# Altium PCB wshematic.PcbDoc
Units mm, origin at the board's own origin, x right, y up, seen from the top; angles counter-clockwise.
Board outline 234.44 x 166.12 mm, 2 copper layers (Top Layer, Bottom Layer); 41 components, 0 nets, 191 pads, 0 vias.
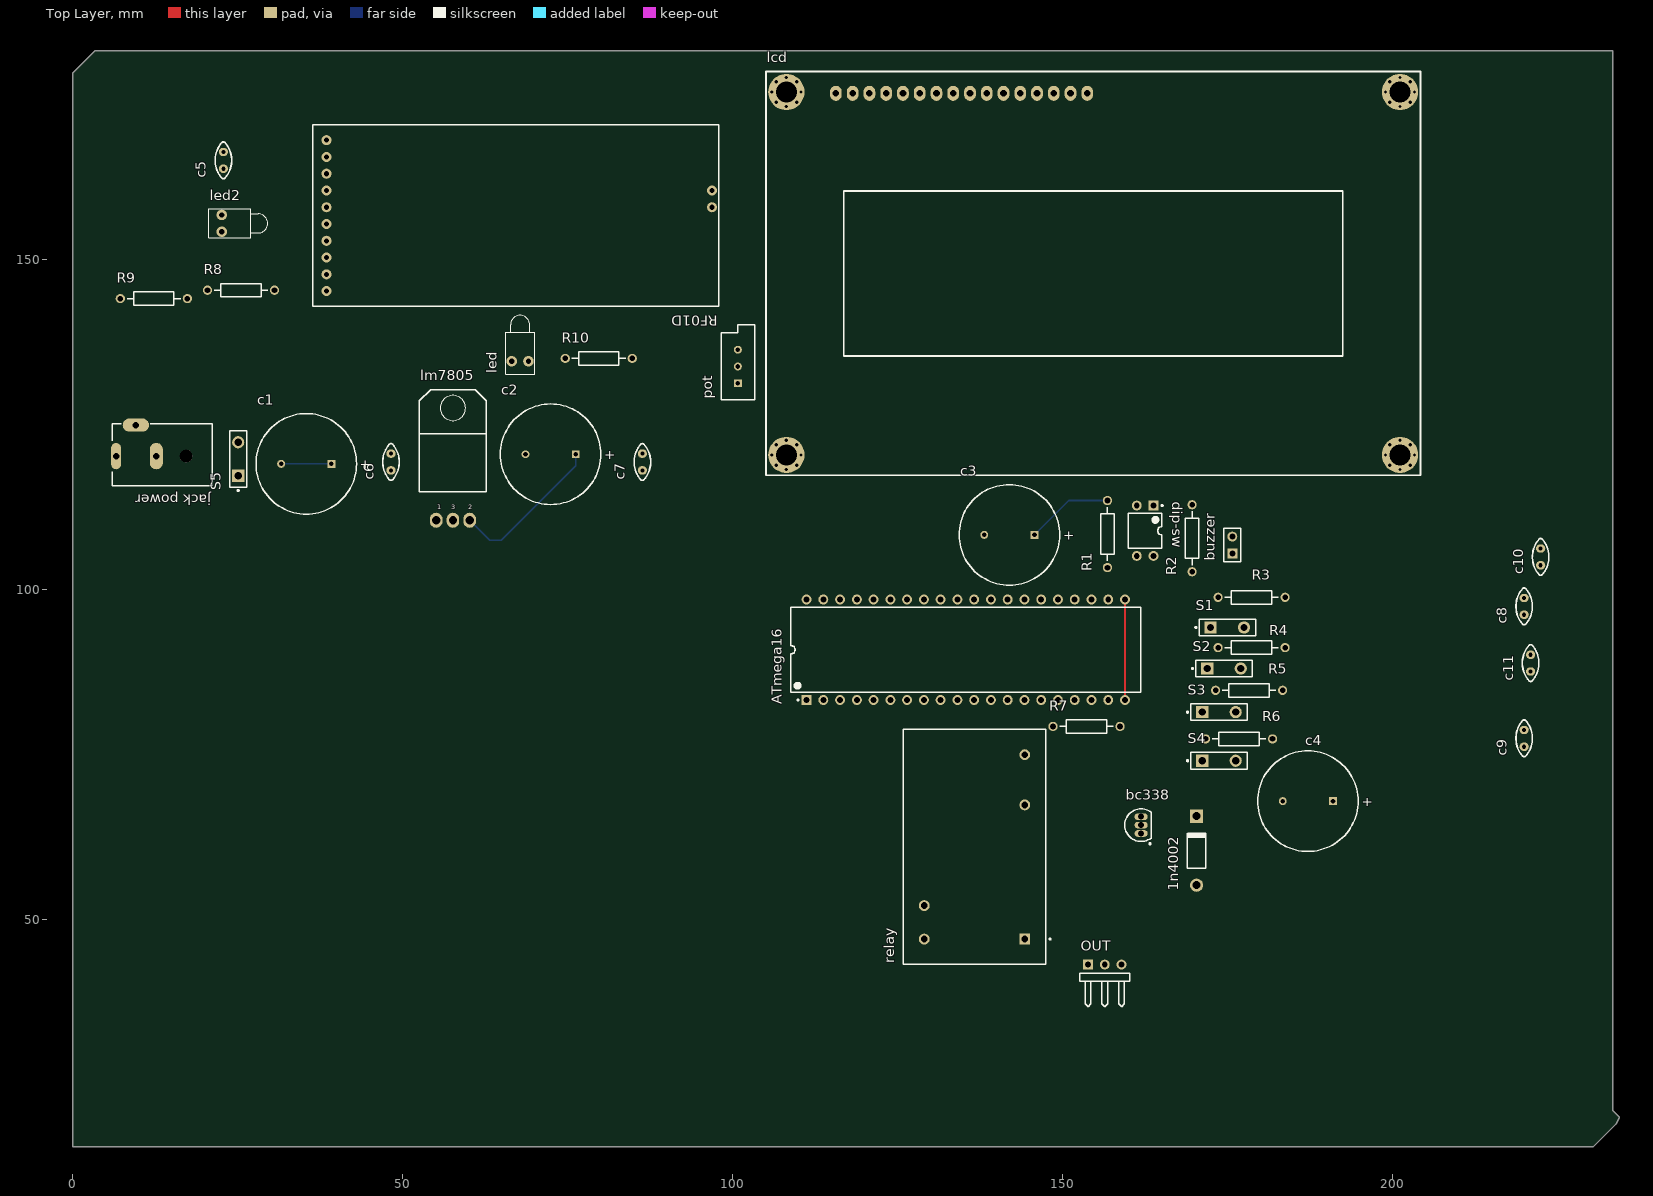
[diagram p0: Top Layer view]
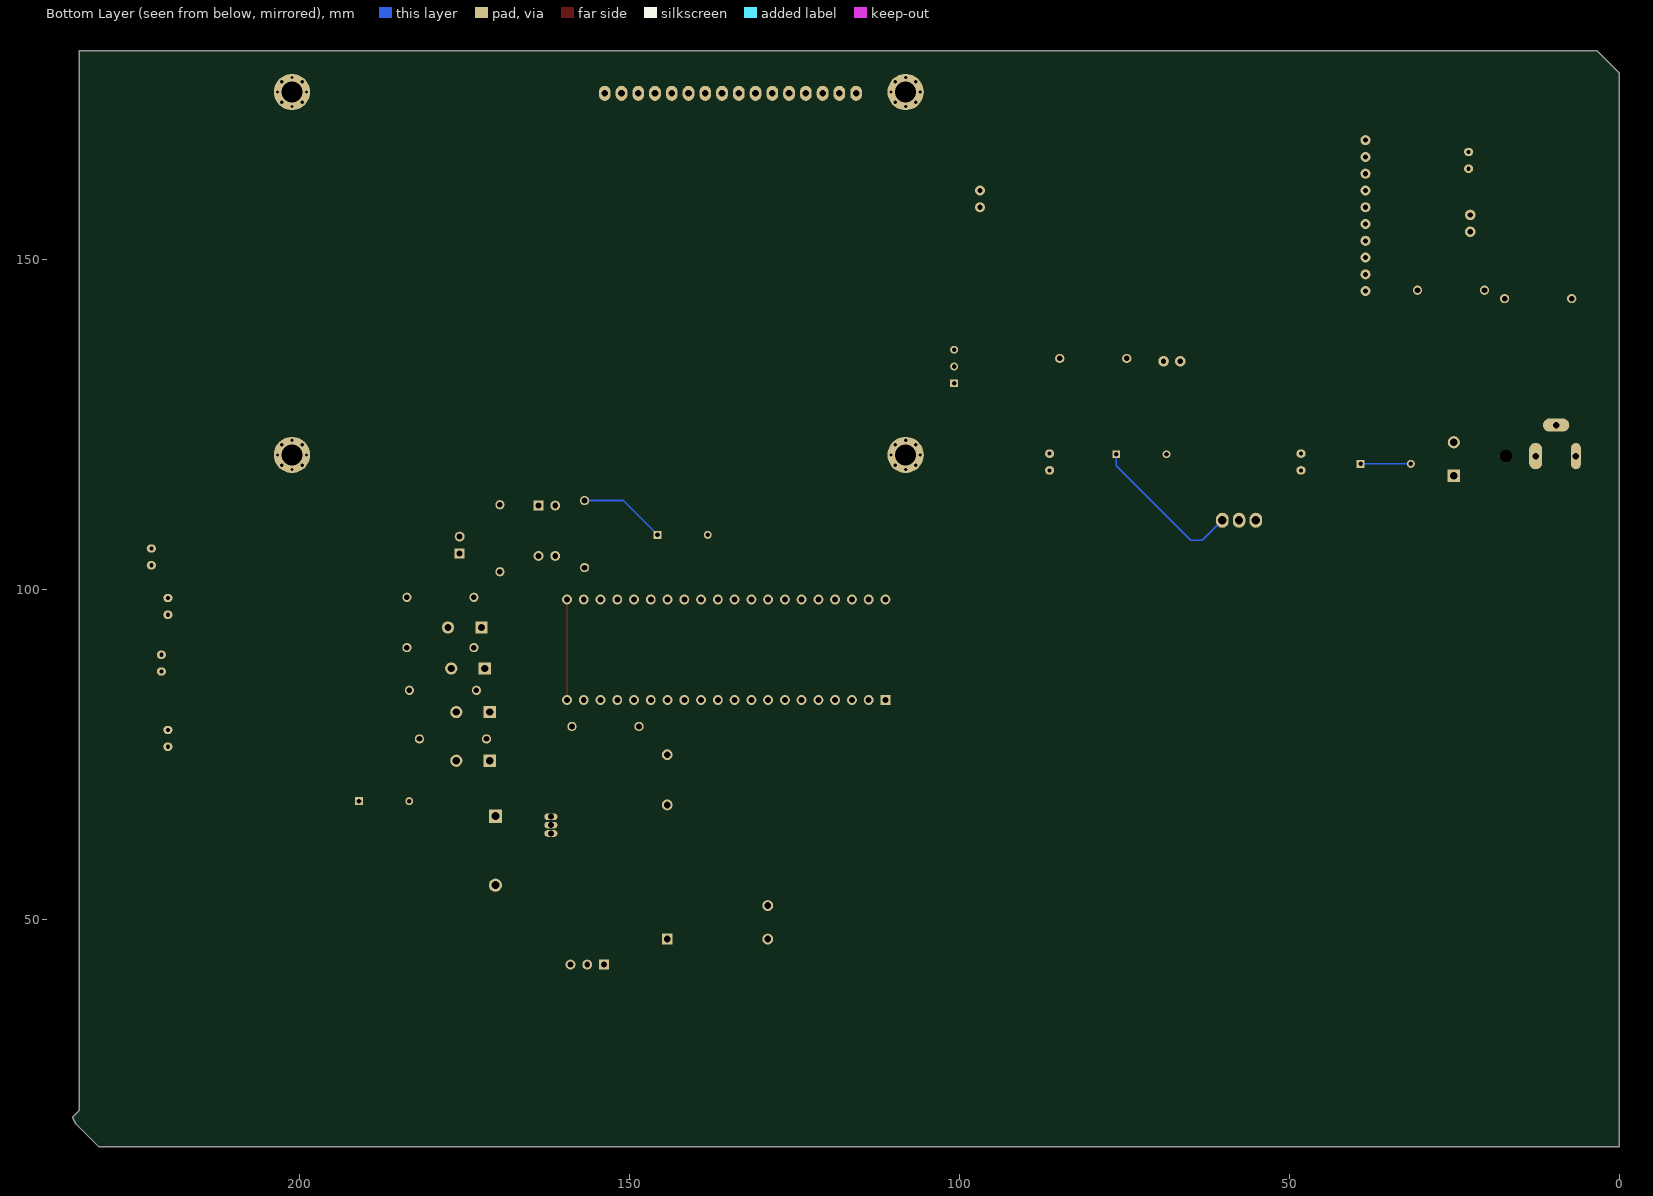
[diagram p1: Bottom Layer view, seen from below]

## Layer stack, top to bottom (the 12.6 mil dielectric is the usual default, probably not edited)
Top Layer: signal copper 0.0356
Dielectric: dielectric 0.32, FR-4, Dk 4.8
Bottom Layer: signal copper 0.0356

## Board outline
234.442,20.066 233.426,21.082 233.426,181.737 3.429,181.737 0,178.308 0,15.621 230.505,15.621 233.934,19.05

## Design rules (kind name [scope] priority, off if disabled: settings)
Clearance [All] p1: gap=0.254
Height [All] p1: minheight=0 maxheight=64 prefheight=12.7
PolygonConnect [All] p1: connectstyle=Relief reliefconductorwidth=0.254 reliefentries=4 polygonreliefangle="90 Angle"
RoutingVias [All] p1: holewidth=0.711 width=1.27 viastyle="Through Hole" minholewidth=0.711 minwidth=1.27 maxholewidth=0.711 maxwidth=1.27
SilkscreenOverComponentPads [All] p1: minsilkscreentomaskgap=0.254
SolderMaskExpansion [All] p1: expansion=0.102
TestPointUsage FabricationTestPointUsage [All] p1: valid=0 allowmultiple=FALSE
Testpoint FabricationTestpoint [All] p1: side=3 testpointundercomponent=TRUE minsize=1.016 maxsize=2.54 preferedsize=1.524 minholesize=0 maxholesize=1.016 preferedholesize=0.813 testpointgrid=0.025 style=297 order=0123456789
Width [All] p1: maxlimit=0.254 minlimit=0.254 preferedwidth=0.254
22 further rules are at their usual default settings.

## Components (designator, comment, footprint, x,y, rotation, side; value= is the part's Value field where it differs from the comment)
1n4002 "Comment" DO-41 170.35,60.475 r90 top
ATmega16 "Comment" 40P6 135.375,90.925 r90 top
bc338 "Comment" TO-92A 161.95,64.35 r0 top
buzzer "Comment" HDR1X2 175.768,105.537 r90 top
c1 "Comment" RB7.6-15 35.425,119.1 r0 top
c2 "Comment" RB7.6-15 72.45,120.55 r0 top
c3 "Comment" RB7.6-15 141.986,108.331 r0 top
c4 "Comment" RB7.6-15 187.225,67.975 r0 top
c5 "Comment" "Cap - 100nF" 22.86,165.1 r90 top
c6 "Comment" "Cap - 100nF" 48.26,119.38 r90 top
c7 "Comment" "Cap - 100nF" 86.36,119.38 r90 top
c8 "Comment" "Cap - 100nF" 220,97.5 r90 top
c9 "Comment" "Cap - 100nF" 220,77.5 r90 top
c10 "Comment" "Cap - 100nF" 222.5,105 r90 top
c11 "Comment" "Cap - 100nF" 220.98,88.9 r90 top
Designator73 "Comment" PCBComponent_1#1 48.05,81.475 r0 top
dip-sw "Comment" DIP-4 162.56,108.966 r270 top
"jack power" "Comment" "Power Jack" 21.2,120.275 r180 top
lcd "Comment" "LCD 20x4" 154.686,147.955 r0 top
led "Comment" LED-1 67.825,134.65 r90 top
led2 "Comment" LED-1 22.625,155.55 r0 top
lm7805 "Comment" "78XXCV - Right" 57.65,110.55 r0 top
OUT "Comment" HDR1X3H 153.9,43.2 r0 top
pot "Comment" VR5 100.838,133.858 r90 top
R1 "Comment" AXIAL-0.4 156.845,108.458 r90 top
R2 "Comment" AXIAL-0.4 169.672,107.823 r90 top
R3 "Comment" AXIAL-0.4 178.693,98.872 r0 top
R4 "Comment" AXIAL-0.4 178.693,91.252 r0 top
R5 "Comment" AXIAL-0.4 178.312,84.775 r0 top
R6 "Comment" AXIAL-0.4 176.788,77.409 r0 top
R7 "Comment" AXIAL-0.4 153.675,79.3 r0 top
R8 "Comment" AXIAL-0.4 25.527,145.415 r0 top
R9 "Comment" AXIAL-0.4 12.319,144.145 r0 top
R10 "Comment" AXIAL-0.4 79.75,135.075 r0 top
relay "Comment" MODULE5B 136.7,61.05 r90 top
RF01D "Comment" PCBComponent_1#2 66.421,157.988 r180 top
S1 "Comment" SPST-2 175.01,94.3 r0 top
S2 "Comment" SPST-2 174.502,88.077 r0 top
S3 "Comment" SPST-2 173.74,81.473 r0 top
S4 "Comment" SPST-2 173.74,74.107 r0 top
S5 "Comment" SPST-2 25.1,119.825 r90 top

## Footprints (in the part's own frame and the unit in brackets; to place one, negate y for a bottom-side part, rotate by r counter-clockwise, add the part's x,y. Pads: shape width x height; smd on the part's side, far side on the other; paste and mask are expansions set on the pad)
40P6 [mm] "DIP, 40-Leads, Row Spacing 15.24mm, Pitch 2.54mm, Body 52.2x13.95mm"
  rect 1.5x1.5 hole 0.9: 1(-7.62,24.13)
  round 1.5 hole 0.9: 2(-7.62,21.59) 3(-7.62,19.05) 4(-7.62,16.51) 5(-7.62,13.97) 6(-7.62,11.43) 7(-7.62,8.89) 8(-7.62,6.35) 9(-7.62,3.81) 10(-7.62,1.27) 11(-7.62,-1.27) 12(-7.62,-3.81) 13(-7.62,-6.35) 14(-7.62,-8.89) 15(-7.62,-11.43) 16(-7.62,-13.97) 17(-7.62,-16.51) 18(-7.62,-19.05) 19(-7.62,-21.59) 20(-7.62,-24.13) 21(7.62,-24.13) 22(7.62,-21.59) 23(7.62,-19.05) 24(7.62,-16.51) 25(7.62,-13.97) 26(7.62,-11.43) 27(7.62,-8.89) 28(7.62,-6.35) 29(7.62,-3.81) 30(7.62,-1.27) 31(7.62,1.27) 32(7.62,3.81) 33(7.62,6.35) 34(7.62,8.89) 35(7.62,11.43) 36(7.62,13.97) 37(7.62,16.51) 38(7.62,19.05) 39(7.62,21.59) 40(7.62,24.13)
  silkscreen extent -7.74,-26.5 6.45,26.5, body extent -7.05,-26.47 7.05,26.47, height 4.83
"78XXCV - Right" [mil] "Right Angle"
  oval 75x90 hole 50: 1(-100,0) 2(100,0) 3(0,0)
  silkscreen extent -201,170 200,780, body extent -198,-8 202,776, height 175
AXIAL-0.4 [mm] "Axial Device, Thru-Hole; 2 Leads; 0.4 in Pin Spacing"
  round 1.4 hole 0.85: 1(-5.08,0) 2(5.08,0)
  silkscreen extent -4.06,-1.02 4.06,1.02
"Cap - 100nF" [mil]
  oval 50x55 hole 25: 1(-50,0) 2(50,0)
  silkscreen extent -110,-49 110,49, body extent -115,-34 115,33, height 272
DIP-4 [mm] "DIP; 4 Leads; Row Spacing 7.62 mm; Pitch 2.54 mm"
  rect 1.5x1.5 hole 0.9: 1(-3.81,1.27)
  round 1.5 hole 0.9: 2(-3.81,-1.27) 3(3.81,-1.27) 4(3.81,1.27)
  silkscreen extent -3.93,-2.55 2.65,2.7, body extent -3.15,-2.5 3.15,2.5, height 5.6
DO-41 [mm] "Diode, Axial; Body 5.2 x 2.7 mm (LxDia. max), Lead Dia. 0.86 mm (max)"
  round 2 hole 1.2: 1(-5.23,0)
  rect 2x2 hole 1.2: 2(5.23,0)
  silkscreen extent -2.65,-1.4 2.75,1.4
HDR1X2 [mm] "Connector; Header; 2 Position"
  rect 1.5x1.5 hole 0.9: 1(0,0)
  round 1.5 hole 0.9: 2(2.54,0)
  silkscreen extent -1.27,-1.27 3.81,1.27
HDR1X3H [mm] "Connector; Header; 3 Position; Right Angle"
  rect 1.5x1.5 hole 0.9: 1(0,0)
  round 1.5 hole 0.9: 2(2.54,0) 3(5.08,0)
  silkscreen extent -1.27,-6.35 6.35,-1.27
"LCD 20x4" [mm]
  oval 1.778x2.286 hole 1.016: 1(-39,27.3) 2(-36.46,27.3) 3(-33.92,27.3) 4(-31.38,27.3) 5(-28.84,27.3) 6(-26.3,27.3) 7(-23.76,27.3) 8(-21.22,27.3) 9(-18.68,27.3) 10(-16.14,27.3) 11(-13.6,27.3) 12(-11.06,27.3) 13(-8.52,27.3) 14(-5.98,27.3) 15(-3.44,27.3) 16(-0.9,27.3)
  round 1 hole 0.5: MH(-48.7,-27.5) MH(-48.7,27.5) MH(-48.056,-29.056) MH(-48.056,-25.944) MH(-48.056,25.944) MH(-48.056,29.056) MH(-46.5,-29.7) MH(-46.5,-25.3) MH(-46.5,25.3) MH(-46.5,29.7) MH(-44.944,-29.056) MH(-44.944,-25.944) MH(-44.944,25.944) MH(-44.944,29.056) MH(-44.3,-27.5) MH(-44.3,27.5) MH(44.3,-27.5) MH(44.3,27.5) MH(44.944,-29.056) MH(44.944,-25.944) MH(44.944,25.944) MH(44.944,29.056) MH(46.5,-29.7) MH(46.5,-25.3) MH(46.5,25.3) MH(46.5,29.7) MH(48.056,-29.056) MH(48.056,-25.944) MH(48.056,25.944) MH(48.056,29.056) MH(48.7,-27.5) MH(48.7,27.5)
  round 5.5 hole 3.2: MH(-46.5,-27.5) MH(-46.5,27.5) MH(46.5,-27.5) MH(46.5,27.5)
  silkscreen extent -49.6,-30.6 49.6,30.6, body extent -49,-30 49,30, height 26.17
LED-1 [mm] "LED; 2 Leads"
  round 1.6 hole 0.8: 1(0,1.27) 2(0,-1.27)
  silkscreen extent -2,-2.2 6.95,2.2
MODULE5B [mm] "DIP; 5 Round Pins; Row Space 15.24 mm; Pitch 2.54 mm"
  rect 1.65x1.65 hole 1: 1(-13.97,-7.62)
  round 1.65 hole 1: 2(-13.97,7.62) 3(-8.89,7.62) 4(13.97,-7.62) 5(6.35,-7.62)
  silkscreen extent -17.8,-11.58 17.8,10.8, body extent -17.8,-10.8 17.8,10.8, height 14
PCBComponent_1#1 [mil]
  round 60 hole 30: 0(-18602.36,-40059.06) 1(-18700.79,-40059.06)
  silkscreen extent -18760,-40114 -18539,-40000
PCBComponent_1#2 [mil]
  round 60 hole 30: 1(1100,500) 2(1100,400) 3(1100,300) 4(1100,200) 5(1100,100) 6(1100,0) 7(1100,-100) 8(1100,-200) 9(1100,-300) 10(1100,-400) 11(-1200,0) 12(-1200,-100)
  silkscreen extent -1240,-492 1181,591
"Power Jack" [mm] "Power Adaptor Jack"
  oval 1.5x4 hole 1: 1(14.605,0)
  oval 2x4 hole 1: 2(8.5,0)
  oval 4x2 hole 1: 3(11.6,-4.7)
  round 1.9 hole 2: MH(4,0)
  silkscreen extent 0,-4.9 15.2,4.5, body extent 0,-4.9 15.2,4.5, height 11
RB7.6-15 [mm] "Polarized Capacitor (Radial); 2 Leads"
  rect 1.2x1.2 hole 0.7: 1(3.81,0)
  round 1.2 hole 0.7: 2(-3.81,0)
  silkscreen extent -7.62,-7.62 7.62,7.62
SPST-2 [mm] "Switch; 2 Leads"
  rect 1.85x1.85 hole 1.1: 1(-2.54,0)
  round 1.85 hole 1.1: 2(2.54,0)
  silkscreen extent -4.89,-1.27 4.28,1.27
TO-92A [mm] "TO, Flat Index; 3 In-Line, Axial Leads; Body Dia. 4.5mm; Leads 0.51 x 0.48 mm (max)"
  oval 2x1 hole 0.9: 1(0,-1.27) 2(0,0) 3(0,1.27)
  silkscreen extent -2.48,-2.95 1.5,2.48, body extent -2.5,-2.5 1.5,2.5, height 6.86
VR5 [mm] "Thru-Hole; 3 Leads"
  rect 1.2x1.2 hole 0.7: 1(-2.54,0)
  round 1.2 hole 0.7: 2(0,0) 3(2.54,0)
  silkscreen extent -5.08,-2.54 6.35,2.54

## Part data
1n4002: library part "Diode 1N4002"
bc338: library part 2N3904
c1 c2 c3 c4: library part "Cap Pol1"
led led2: library part LED1
lm7805: library part L78XXCV
pot: library part RPot
R1 R2 R3 R4 R5 R6 R7 R8 R9 R10: library part Res2
relay: library part Relay
S1 S2 S3 S4 S5: library part SW-PB

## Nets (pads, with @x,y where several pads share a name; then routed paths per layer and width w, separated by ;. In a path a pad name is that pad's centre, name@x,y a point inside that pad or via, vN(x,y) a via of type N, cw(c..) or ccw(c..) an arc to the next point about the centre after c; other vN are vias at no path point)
pads on no net: 1n4002.1 1n4002.2 "jack power.1" "jack power.2" "jack power.3" "jack power.MH" ATmega16.1 ATmega16.2 ATmega16.3 ATmega16.4 ATmega16.5 ATmega16.6 ATmega16.7 ATmega16.8 ATmega16.9 ATmega16.10 ATmega16.11 ATmega16.12 ATmega16.13 ATmega16.14 ATmega16.15 ATmega16.16 ATmega16.17 ATmega16.18 ATmega16.19 ATmega16.20 ATmega16.21 ATmega16.22 ATmega16.23 ATmega16.24 ATmega16.25 ATmega16.26 ATmega16.27 ATmega16.28 ATmega16.29 ATmega16.30 ATmega16.31 ATmega16.32 ATmega16.33 ATmega16.34 ATmega16.35 ATmega16.36 ATmega16.37 ATmega16.38 ATmega16.39 ATmega16.40 bc338.1 bc338.2 bc338.3 buzzer.1 buzzer.2 c1.1 c1.2 c2.1 c2.2 c3.1 c3.2 c4.1 c4.2 c5.1 c5.2 c6.1 c6.2 c7.1 c7.2 c8.1 c8.2 c9.1 c9.2 c10.1 c10.2 c11.1 c11.2 Designator73.0 Designator73.1 dip-sw.1 dip-sw.2 dip-sw.3 dip-sw.4 lcd.1 lcd.2 lcd.3 lcd.4 lcd.5 lcd.6 lcd.7 lcd.8 lcd.9 lcd.10 lcd.11 lcd.12 lcd.13 lcd.14 lcd.15 lcd.16 lcd.MH led2.1 led2.2 led.1 led.2 lm7805.1 lm7805.2 lm7805.3 OUT.1 OUT.2 OUT.3 pot.1 pot.2 pot.3 R1.1 R1.2 R2.1 R2.2 R3.1 R3.2 R4.1 R4.2 R5.1 R5.2 R6.1 R6.2 R7.1 R7.2 R8.1 R8.2 R9.1 R9.2 R10.1 R10.2 relay.1 relay.2 relay.3 relay.4 relay.5 RF01D.1 RF01D.2 RF01D.3 RF01D.4 RF01D.5 RF01D.6 RF01D.7 RF01D.8 RF01D.9 RF01D.10 RF01D.11 RF01D.12 S1.1 S1.2 S2.1 S2.2 S3.1 S3.2 S4.1 S4.2 S5.1 S5.2
copper on no net: | length 59.8
  Top Layer w0.254: 159.505,83.305 159.505,98.545
  Bottom Layer w0.254: 31.615,119.1 39.235,119.1 ; 60.19,110.55 63.24,107.5 64.949,107.5 76.26,118.811 76.26,120.55 ; 145.796,108.331 151.003,113.538 156.845,113.538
